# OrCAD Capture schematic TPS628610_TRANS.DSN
size E; title: TPS628610:1.8-V to 5.5-V Input, 0.6-/1-A Synchronous Step-Down; rev: 1.0; note: Datasheet:SLUSDU8   EVM: SLUUC85A; note: Synchronous Step Down Converter
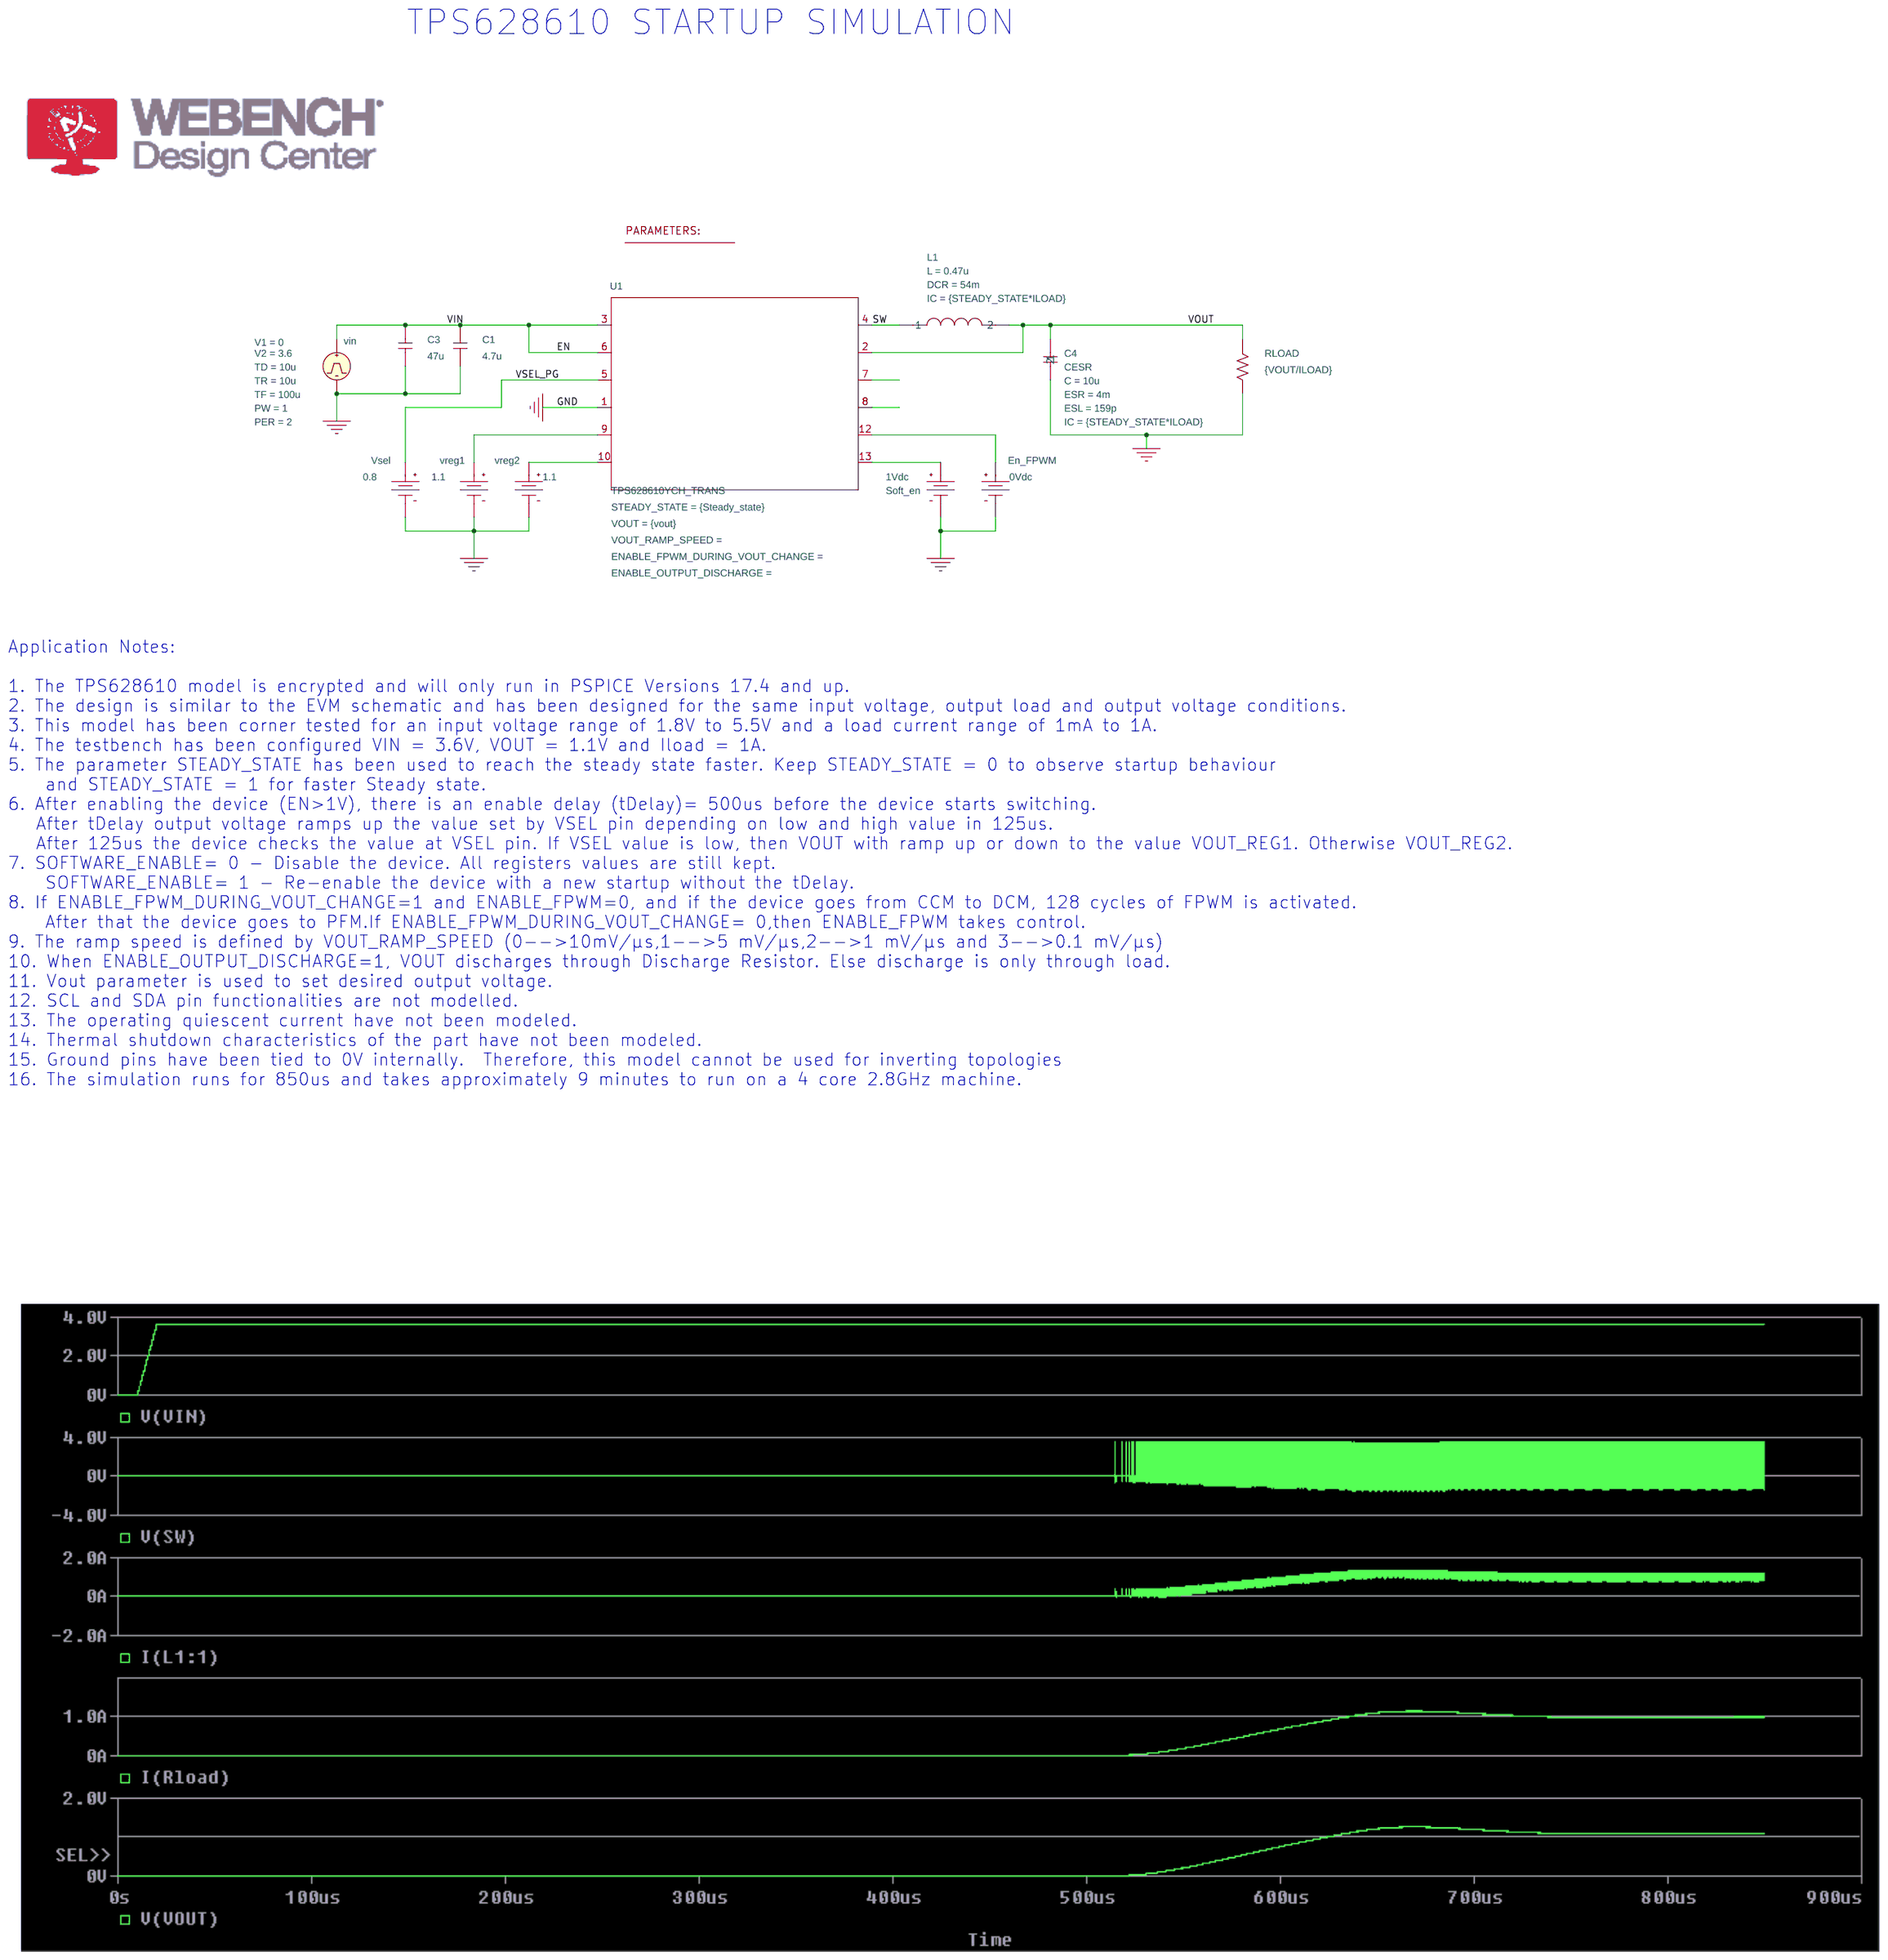
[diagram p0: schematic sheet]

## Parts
2  PARAM
C1  4.7u  [RAD/CK05]
C3  47u  [RAD/CK05]
C4  CESR
En_FPWM  VDC
L1  LDCR
RLOAD  {VOUT/ILOAD}  [AX/RC05]
Soft_en  VDC
U1  TPS628610YCH_TRANS  [YCH0008ACAC]
vin  VPULSE
vreg1  VDC
vreg2  VDC
Vsel  VDC

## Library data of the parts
2 = PARAM: ILOAD: 1; STEADY_STATE: 0; VOUT: 1.1
C1 C3 = C
C4 = CESR: C: 10u; ESL: 159p; ESR: 4m; IC: {STEADY_STATE*ILOAD}; PSpiceTemplate: X^@REFDES %1 %2 @MODEL PARAMS: ?C|C=@C||C=10U| ?ESR|ESR=@ESR||ESR=2M| ?ESL|ESL=@ESL||ESL=1N| ?IC|IC=@IC||IC=0|
En_FPWM = VDC: DC: 0Vdc
L1 = LDCR: DCR: 54m; IC: {STEADY_STATE*ILOAD}; L: 0.47u
RLOAD = R
Soft_en = VDC: DC: 1Vdc
U1 = TPS628610YCH_TRANS: STEADY_STATE: {Steady_state}; VOUT: {vout}
vin = VPULSE: PER: 2; PW: 1; TD: 10u; TF: 100u; TR: 10u; V1: 0; V2: 3.6
vreg1 vreg2 = VDC: DC: 1.1
Vsel = VDC: DC: 0.8

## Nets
0: C1.1 C3.1 C4.2 En_FPWM.1(-) RLOAD.2 Soft_en.1(-) U1.1(GND) vin.2(-) vreg1.1(-) vreg2.1(-) Vsel.1(-)
EN: C1.2 C3.2 U1.3(VIN) U1.6(EN) vin.1(+)
SW: L1.1 U1.4(SW)
VOUT: C4.1 L1.2 RLOAD.1 U1.2(VOS)
VSEL_PG: U1.5(VSEL) Vsel.0(+)
N16792685: Soft_en.0(+) U1.13(SOFTWARE_ENABLE)
N16792757: En_FPWM.0(+) U1.12(ENABLE_FPWM)
N16793679: U1.9(VOUT_REG1) vreg1.0(+)
N16793683: U1.10(VOUT_REG2) vreg2.0(+)

Not connected (* = marked no-connect by the designer): U1 7(SDA) 8(SCL)

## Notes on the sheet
- TPS628610 STARTUP SIMULATION
- Application Notes:
  1. The TPS628610 model is encrypted and will only run in PSPICE Versions 17.4 and up.
  2. The design is similar to the EVM schematic and has been designed for the same input voltage, output load and output voltage conditions.
  3. This model has been corner tested for an input voltage range of 1.8V to 5.5V and a load current range of 1mA to 1A.
  4. The testbench has been configured VIN = 3.6V, VOUT = 1.1V and Iload = 1A.
  5. The parameter STEADY_STATE has been used to reach the steady state faster. Keep STEADY_STATE = 0 to observe startup behaviour
      and STEADY_STATE = 1 for faster Steady state.
  6. After enabling the device (EN>1V), there is an enable delay (tDelay)= 500us before the device starts switching.
     After tDelay output voltage ramps up the value set by VSEL pin depending on low and high value in 125us.
     After 125us the device checks the value at VSEL pin. If VSEL value is low, then VOUT with ramp up or down to the value VOUT_REG1. Otherwise VOUT_REG2.
  7. SOFTWARE_ENABLE= 0 - Disable the device. All registers values are still kept.
      SOFTWARE_ENABLE= 1 - Re-enable the device with a new startup without the tDelay.
  8. If ENABLE_FPWM_DURING_VOUT_CHANGE=1 and ENABLE_FPWM=0, and if the device goes from CCM to DCM, 128 cycles of FPWM is activated.
      After that the device goes to PFM.If ENABLE_FPWM_DURING_VOUT_CHANGE= 0,then ENABLE_FPWM takes control.
  9. The ramp speed is defined by VOUT_RAMP_SPEED (0-->10mV/µs,1-->5 mV/µs,2-->1 mV/µs and 3-->0.1 mV/µs)
  10. When ENABLE_OUTPUT_DISCHARGE=1, VOUT discharges through Discharge Resistor. Else discharge is only through load.
  11. Vout parameter is used to set desired output voltage.
  12. SCL and SDA pin functionalities are not modelled.
  13. The operating quiescent current have not been modeled.
  14. Thermal shutdown characteristics of the part have not been modeled.
  15. Ground pins have been tied to 0V internally.  Therefore, this model cannot be used for inverting topologies
  16. The simulation runs for 850us and takes approximately 9 minutes to run on a 4 core 2.8GHz machine.
